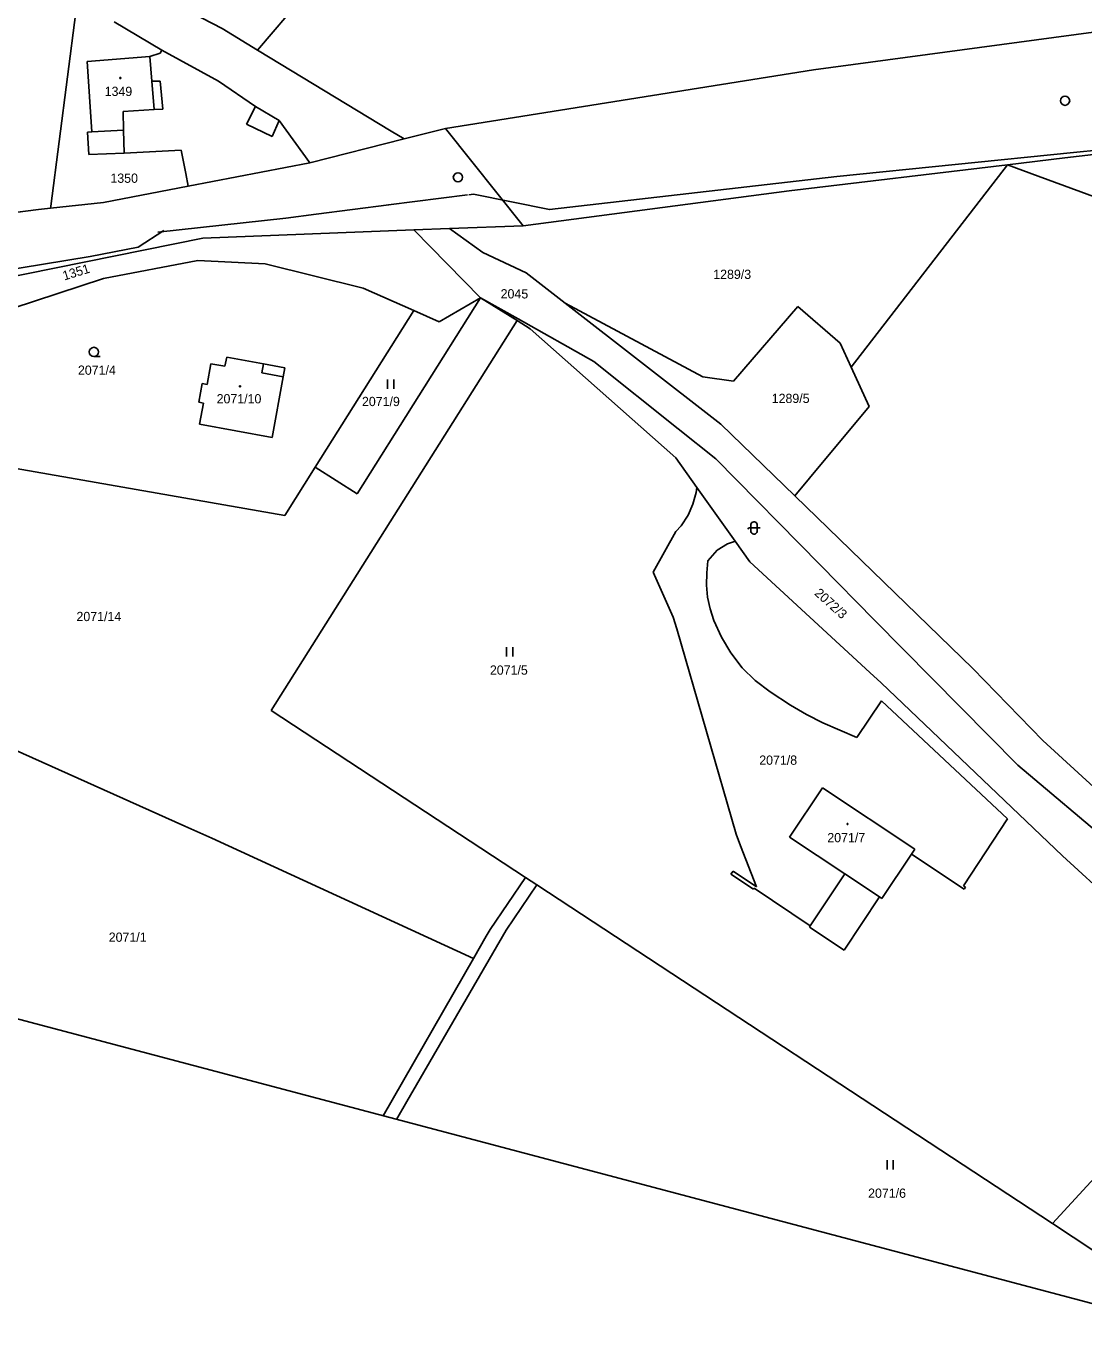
# Model space of a CAD drawing. Extents: x -805011 to -803920, y -1150790 to -1150234.
# Drawn here: x -804600.8 to -804429.5, y -1150682.7 to -1150469 of the extents above; entities that cross this region are included whole.
import ezdxf

# ---------------------------------------------------------------- set-up
doc = ezdxf.new("R2010")
doc.units = 0
for name, color, linetype in [('Default', 7, 'Continuous'), ('formát', 7, 'Continuous'), ('kilometráž - vrstava 7', 7, 'Continuous'), ('kn_celek - Cisla pozemkovych parcel', 7, 'Continuous'), ('kn_celek - Cisla stavebnich parcel', 7, 'Continuous'), ('kn_celek - Hranice parcel', 7, 'Continuous'), ('kn_celek - Vnitrni kresby', 7, 'Continuous'), ('kn_celek - Znacky budov', 7, 'Continuous'), ('kn_celek - Znacky kultur', 7, 'Continuous'), ('plochy - SZDC', 7, 'Continuous'), ('PSR_C2_2_trasa_Vimperk - Kabelová trasa', 7, 'Continuous')]:
    doc.layers.add(name, color=color, linetype=linetype)

# ---------------------------------------------------------------- blocks, each defined once
blk = doc.blocks.new('304')
at = {"layer": 'Default'}
blk.add_line((-0.1, 0), (9.9, 0), dxfattribs=at)
blk.add_circle((-0.1, 7.5), 7.5, dxfattribs=at)
blk = doc.blocks.new('306')
at = {"layer": 'Default'}
for p, q in [((-5.2, 0), (-5.2, 15)), ((4.8, 0), (4.8, 15))]:
    blk.add_line(p, q, dxfattribs=at)
blk = doc.blocks.new('316')
at = {"layer": 'Default'}
for p, q in [((-8.3, 10), (-10, 8.1)), ((-5, 10), (-8.3, 10)), ((-5, 15.5), (-5, 4.5)), ((-5, 10), (5, 10)), ((0.5, 20), (-0.5, 20)), ((-0.5, 0), (0.5, 0)), ((5, 4.5), (5, 15.5)), ((10, 10), (5, 10))]:
    blk.add_line(p, q, dxfattribs=at)
for centre, start, end in [((-0.5, 15.5), 90, 180), ((-0.5, 4.5), 180, 270), ((0.5, 15.5), 0, 90), ((0.5, 4.5), 270, 0)]:
    blk.add_arc(centre, 4.5, start, end, dxfattribs=at)
blk = doc.blocks.new('402')
at = {"layer": 'Default'}
for p, q in [((-0.8, 0.8), (0.7, 0.8)), ((-0.8, 0.8), (-0.8, -0.7)), ((0.7, 0.8), (0.7, -0.7)), ((0.7, -0.7), (-0.8, -0.7))]:
    blk.add_line(p, q, dxfattribs=at)

msp = doc.modelspace()

# ---------------------------------------------------------------- linework, layer by layer
at = {"layer": 'formát'}
msp.add_line((-804402.28, -1150682.7), (-805011.32, -1150521.54), dxfattribs=at)
at = {"layer": 'kilometráž - vrstava 7'}
for centre in [(-804432.47, -1150481.04), (-804530.84, -1150493.45)]:
    msp.add_circle(centre, 0.75, dxfattribs=at)
at = {"layer": 'kn_celek - Hranice parcel'}
for p, q in [((-804584.21, -1150461.47), (-804569.06, -1150469.36)), ((-804556.02, -1150464.26), (-804563.32, -1150472.84)), ((-804592.74, -1150466.72), (-804596.82, -1150498.15)), ((-804578.81, -1150472.86), (-804586.55, -1150468.28)), ((-804563.32, -1150472.84), (-804569.06, -1150469.36)), ((-804427.86, -1150469.92), (-804473.24, -1150476.04)), ((-804590.9, -1150474.67), (-804580.76, -1150473.86)), ((-804590.18, -1150486.09), (-804590.9, -1150474.67)), ((-804579.09, -1150473.33), (-804580.76, -1150473.86)), ((-804578.81, -1150472.86), (-804579.09, -1150473.33)), ((-804569.62, -1150477.9), (-804578.81, -1150472.86)), ((-804563.32, -1150472.84), (-804541.68, -1150485.95)), ((-804473.24, -1150476.04), (-804532.83, -1150485.53)), ((-804563.64, -1150481.97), (-804569.62, -1150477.9)), ((-804559.78, -1150484.23), (-804563.64, -1150481.97)), ((-804559.78, -1150484.23), (-804554.84, -1150491.12)), ((-804590.87, -1150486.13), (-804590.18, -1150486.09)), ((-804590.63, -1150489.77), (-804590.87, -1150486.13)), ((-804554.84, -1150491.12), (-804539.55, -1150487.24)), ((-804541.68, -1150485.95), (-804539.55, -1150487.24)), ((-804539.55, -1150487.24), (-804532.83, -1150485.53)), ((-804520.26, -1150501.29), (-804532.83, -1150485.53)), ((-804584.93, -1150489.54), (-804590.63, -1150489.77)), ((-804584.93, -1150489.54), (-804575.7, -1150489.05)), ((-804575.7, -1150489.05), (-804574.95, -1150492.83)), ((-804413.66, -1150488.07), (-804432.51, -1150490.32)), ((-804574.54, -1150494.89), (-804554.84, -1150491.12)), ((-804441.78, -1150491.42), (-804477.16, -1150495.64)), ((-804467.14, -1150524.2), (-804441.78, -1150491.42)), ((-804432.51, -1150490.32), (-804441.78, -1150491.42)), ((-804436.85, -1150493.24), (-804441.78, -1150491.42)), ((-804574.95, -1150492.83), (-804574.54, -1150494.89)), ((-804436.85, -1150493.24), (-804422.59, -1150498.49)), ((-804574.54, -1150494.89), (-804588.25, -1150497.51)), ((-804520.26, -1150501.29), (-804477.16, -1150495.64)), ((-804596.86, -1150498.46), (-804588.25, -1150497.51)), ((-804596.82, -1150498.15), (-804596.86, -1150498.46)), ((-804621.33, -1150501.45), (-804598.8, -1150498.68)), ((-804596.86, -1150498.46), (-804598.8, -1150498.68)), ((-804537.98, -1150501.97), (-804572.18, -1150503.29)), ((-804532.2, -1150501.75), (-804537.98, -1150501.97)), ((-804537.98, -1150501.97), (-804527.18, -1150512.96)), ((-804532.2, -1150501.75), (-804520.26, -1150501.29)), ((-804532.2, -1150501.75), (-804526.8, -1150505.61)), ((-804621.63, -1150513.27), (-804572.18, -1150503.29)), ((-804526.8, -1150505.61), (-804519.81, -1150508.93)), ((-804588.25, -1150509.82), (-804572.97, -1150506.95)), ((-804572.97, -1150506.95), (-804562.06, -1150507.47)), ((-804562.06, -1150507.47), (-804546.21, -1150511.39)), ((-804603.08, -1150514.69), (-804588.25, -1150509.82)), ((-804519.81, -1150508.93), (-804513.46, -1150513.86)), ((-804547.18, -1150544.7), (-804527.18, -1150512.96)), ((-804546.21, -1150511.39), (-804537.98, -1150515.04)), ((-804527.18, -1150512.96), (-804533.87, -1150516.86)), ((-804521.27, -1150516.66), (-804527.18, -1150512.96)), ((-804521.1, -1150516.38), (-804527.18, -1150512.96)), ((-804537.98, -1150515.04), (-804553.97, -1150540.42)), ((-804533.87, -1150516.86), (-804537.98, -1150515.04)), ((-804513.46, -1150513.86), (-804491.17, -1150525.75)), ((-804513.46, -1150513.86), (-804488.22, -1150533.42)), ((-804486.17, -1150526.47), (-804475.79, -1150514.38)), ((-804475.79, -1150514.38), (-804468.92, -1150520.34)), ((-804521.27, -1150516.66), (-804561.12, -1150579.81)), ((-804519.14, -1150517.99), (-804521.27, -1150516.66)), ((-804508.84, -1150523.27), (-804521.1, -1150516.38)), ((-804495.52, -1150538.89), (-804519.14, -1150517.99)), ((-804468.92, -1150520.34), (-804467.14, -1150524.2)), ((-804571.48, -1150527.02), (-804570.86, -1150523.64)), ((-804570.86, -1150523.64), (-804568.59, -1150524.05)), ((-804568.59, -1150524.05), (-804568.31, -1150522.59)), ((-804568.31, -1150522.59), (-804562.34, -1150523.68)), ((-804562.34, -1150523.68), (-804558.87, -1150524.3)), ((-804495.17, -1150534.18), (-804508.84, -1150523.27)), ((-804559.15, -1150525.77), (-804560.94, -1150535.58)), ((-804558.87, -1150524.3), (-804559.15, -1150525.77)), ((-804491.17, -1150525.75), (-804486.17, -1150526.47)), ((-804467.14, -1150524.2), (-804464.21, -1150530.56)), ((-804572.83, -1150529.87), (-804572.28, -1150526.87)), ((-804572.28, -1150526.87), (-804571.48, -1150527.02)), ((-804572.07, -1150530.01), (-804572.83, -1150529.87)), ((-804572.69, -1150533.42), (-804572.07, -1150530.01)), ((-804464.21, -1150530.56), (-804473.9, -1150542.18)), ((-804560.94, -1150535.58), (-804572.69, -1150533.42)), ((-804489.08, -1150539.04), (-804495.17, -1150534.18)), ((-804476.26, -1150545.02), (-804488.22, -1150533.42)), ((-804558.89, -1150548.22), (-804603.64, -1150540.42)), ((-804553.97, -1150540.42), (-804558.89, -1150548.22)), ((-804553.97, -1150540.42), (-804547.18, -1150544.7)), ((-804492.11, -1150543.68), (-804495.52, -1150538.89)), ((-804472.13, -1150556.23), (-804489.08, -1150539.04)), ((-804473.9, -1150542.18), (-804476.26, -1150545.02)), ((-804492.24, -1150544.49), (-804492.76, -1150546.39)), ((-804492.11, -1150543.68), (-804492.24, -1150544.49)), ((-804485.91, -1150552.4), (-804492.11, -1150543.68)), ((-804447.39, -1150573.04), (-804476.26, -1150545.02)), ((-804492.76, -1150546.39), (-804493.54, -1150548.19)), ((-804493.54, -1150548.19), (-804494.66, -1150549.89)), ((-804495.53, -1150550.85), (-804499.22, -1150557.42)), ((-804494.66, -1150549.89), (-804495.53, -1150550.85)), ((-804488.84, -1150553.87), (-804487.15, -1150552.81)), ((-804487.15, -1150552.81), (-804486.21, -1150552.47)), ((-804486.21, -1150552.47), (-804485.91, -1150552.4)), ((-804483.55, -1150555.72), (-804485.91, -1150552.4)), ((-804490.53, -1150557.54), (-804490.33, -1150555.56)), ((-804490.33, -1150555.56), (-804488.84, -1150553.87)), ((-804483.55, -1150555.72), (-804464.09, -1150573.64)), ((-804499.22, -1150557.42), (-804495.98, -1150564.72)), ((-804490.55, -1150559.51), (-804490.53, -1150557.54)), ((-804472.13, -1150556.23), (-804463.32, -1150565.16)), ((-804490.38, -1150561.47), (-804490.55, -1150559.51)), ((-804489.96, -1150563.35), (-804490.38, -1150561.47)), ((-804489.37, -1150565.26), (-804489.96, -1150563.35)), ((-804495.98, -1150564.72), (-804495.35, -1150566.6)), ((-804488.15, -1150567.96), (-804489.37, -1150565.26)), ((-804440.13, -1150588.68), (-804463.32, -1150565.16)), ((-804495.35, -1150566.6), (-804485.74, -1150599.83)), ((-804486.6, -1150570.5), (-804488.15, -1150567.96)), ((-804484.8, -1150572.89), (-804486.6, -1150570.5)), ((-804482.67, -1150574.98), (-804484.8, -1150572.89)), ((-804480.26, -1150576.8), (-804482.67, -1150574.98)), ((-804464.09, -1150573.64), (-804462.26, -1150575.33)), ((-804436.08, -1150584.68), (-804447.39, -1150573.04)), ((-804476.98, -1150578.97), (-804480.26, -1150576.8)), ((-804462.26, -1150575.33), (-804432.9, -1150603.34)), ((-804474.38, -1150580.45), (-804476.98, -1150578.97)), ((-804462.23, -1150578.26), (-804466.23, -1150584.2)), ((-804441.77, -1150597.39), (-804462.23, -1150578.26)), ((-804561.12, -1150579.81), (-804519.91, -1150606.86)), ((-804471.69, -1150581.79), (-804474.38, -1150580.45)), ((-804575.08, -1150598.55), (-804610.41, -1150582.75)), ((-804468.95, -1150583.03), (-804471.69, -1150581.79)), ((-804466.23, -1150584.2), (-804468.95, -1150583.03)), ((-804415.85, -1150603.25), (-804436.08, -1150584.68)), ((-804440.13, -1150588.68), (-804393.29, -1150628.23)), ((-804477.13, -1150600.34), (-804471.79, -1150592.34)), ((-804471.79, -1150592.34), (-804456.81, -1150602.26)), ((-804570.71, -1150600.51), (-804575.08, -1150598.55)), ((-804448.91, -1150608.23), (-804441.77, -1150597.39)), ((-804570.71, -1150600.51), (-804528.34, -1150620)), ((-804485.74, -1150599.83), (-804485.08, -1150601.74)), ((-804477.13, -1150600.34), (-804468.13, -1150606.27)), ((-804485.08, -1150601.74), (-804482.47, -1150608.37)), ((-804457.37, -1150603.1), (-804456.81, -1150602.26)), ((-804462.13, -1150610.26), (-804457.37, -1150603.1)), ((-804457.37, -1150603.1), (-804448.79, -1150608.78)), ((-804432.9, -1150603.34), (-804404.11, -1150629.75)), ((-804525.63, -1150615.27), (-804519.91, -1150606.86)), ((-804519.91, -1150606.86), (-804518.07, -1150608.06)), ((-804486.25, -1150605.84), (-804486.6, -1150606.33)), ((-804486.6, -1150606.33), (-804482.94, -1150608.77)), ((-804482.47, -1150608.37), (-804486.25, -1150605.84)), ((-804473.53, -1150614.37), (-804468.13, -1150606.27)), ((-804518.07, -1150608.06), (-804523.03, -1150615.38)), ((-804518.07, -1150608.06), (-804434.49, -1150662.92)), ((-804482.94, -1150608.77), (-804482.83, -1150608.6)), ((-804482.83, -1150608.6), (-804473.75, -1150614.7)), ((-804448.58, -1150608.45), (-804448.91, -1150608.23)), ((-804448.79, -1150608.78), (-804448.58, -1150608.45)), ((-804468.27, -1150618.64), (-804462.53, -1150609.99)), ((-804462.53, -1150609.99), (-804462.13, -1150610.26)), ((-804523.03, -1150615.38), (-804539.11, -1150643.15)), ((-804526.25, -1150616.36), (-804525.63, -1150615.27)), ((-804473.75, -1150614.7), (-804473.88, -1150614.9)), ((-804473.88, -1150614.9), (-804468.27, -1150618.64)), ((-804473.75, -1150614.7), (-804473.53, -1150614.37)), ((-804528.34, -1150620), (-804526.25, -1150616.36)), ((-804542.97, -1150645.47), (-804528.34, -1150620)), ((-804434.49, -1150662.92), (-804404.11, -1150629.75)), ((-804539.11, -1150643.15), (-804540.79, -1150646.05)), ((-804407.44, -1150680.8), (-804434.49, -1150662.92))]:
    msp.add_line(p, q, dxfattribs=at)
at = {"layer": 'kn_celek - Vnitrni kresby'}
for p, q in [((-804580.76, -1150473.86), (-804580.44, -1150477.88)), ((-804580.44, -1150477.88), (-804579.07, -1150477.87)), ((-804580.05, -1150482.49), (-804580.44, -1150477.88)), ((-804579.07, -1150477.87), (-804578.68, -1150482.4)), ((-804580.05, -1150482.49), (-804585.1, -1150482.81)), ((-804585.02, -1150485.8), (-804585.1, -1150482.81)), ((-804580.05, -1150482.49), (-804578.68, -1150482.4)), ((-804563.64, -1150481.97), (-804565.11, -1150484.86)), ((-804565.11, -1150484.86), (-804560.95, -1150486.84)), ((-804560.95, -1150486.84), (-804559.78, -1150484.23)), ((-804590.18, -1150486.09), (-804585.02, -1150485.8)), ((-804585.02, -1150485.8), (-804584.93, -1150489.54)), ((-804562.34, -1150523.68), (-804562.63, -1150525.14)), ((-804562.63, -1150525.14), (-804559.15, -1150525.77)), ((-804462.53, -1150609.99), (-804468.13, -1150606.27))]:
    msp.add_line(p, q, dxfattribs=at)
at = {"layer": 'plochy - SZDC'}
for p, q in [((-804427.86, -1150469.92), (-804473.24, -1150476.04)), ((-804473.24, -1150476.04), (-804532.83, -1150485.53)), ((-804539.55, -1150487.24), (-804554.84, -1150491.12)), ((-804532.83, -1150485.53), (-804539.55, -1150487.24)), ((-804532.83, -1150485.53), (-804520.26, -1150501.29)), ((-804520.26, -1150501.29), (-804532.83, -1150485.53)), ((-804432.51, -1150490.32), (-804413.66, -1150488.07)), ((-804554.84, -1150491.12), (-804574.54, -1150494.89)), ((-804477.16, -1150495.64), (-804441.78, -1150491.42)), ((-804441.78, -1150491.42), (-804432.51, -1150490.32)), ((-804574.54, -1150494.89), (-804588.25, -1150497.51)), ((-804520.26, -1150501.29), (-804477.16, -1150495.64)), ((-804588.25, -1150497.51), (-804596.86, -1150498.46)), ((-804598.8, -1150498.68), (-804621.33, -1150501.45)), ((-804596.86, -1150498.46), (-804598.8, -1150498.68)), ((-804572.18, -1150503.29), (-804537.98, -1150501.97)), ((-804537.98, -1150501.97), (-804532.2, -1150501.75)), ((-804532.2, -1150501.75), (-804520.26, -1150501.29)), ((-804621.63, -1150513.27), (-804572.18, -1150503.29))]:
    msp.add_line(p, q, dxfattribs=at)
at = {"layer": 'PSR_C2_2_trasa_Vimperk - Kabelová trasa'}
for p, q in [((-804542.06, -1150497.91), (-804553.82, -1150499.4)), ((-804529.29, -1150496.27), (-804542.1, -1150497.89)), ((-804558.71, -1150500.08), (-804579.48, -1150502.32)), ((-804558.71, -1150500.08), (-804553.82, -1150499.4)), ((-804582.65, -1150504.79), (-804578.5, -1150502.04)), ((-804617.64, -1150510.74), (-804590.41, -1150506.27)), ((-804582.65, -1150504.79), (-804590.41, -1150506.27))]:
    msp.add_line(p, q, dxfattribs=at)
msp.add_lwpolyline([(-804529.08, -1150496.27), (-804528.3, -1150496.2), (-804516.01, -1150498.69), (-804469.46, -1150493.33), (-804431.1, -1150489.42), (-804404.84, -1150486.85), (-804374.84, -1150483.32), (-804363.68, -1150482.47), (-804347.01, -1150481.54), (-804340.82, -1150481.2), (-804326.33, -1150481.6), (-804317.79, -1150482), (-804308.33, -1150484.14), (-804289, -1150488.51)], dxfattribs=at)

# ---------------------------------------------------------------- block references
at = {"layer": 'kn_celek - Znacky budov', "xscale": 0.1, "yscale": 0.10000000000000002}
for p in [(-804585.55, -1150477.36), (-804566.14, -1150527.32), (-804467.72, -1150598.21)]:
    msp.add_blockref('402', p, dxfattribs=at)
at = {"layer": 'kn_celek - Znacky kultur', "xscale": 0.1, "yscale": 0.10000000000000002}
for name, p in [('304', (-804589.82, -1150522.49)), ('306', (-804541.72, -1150527.71)), ('316', (-804482.86, -1150551.25)), ('306', (-804522.44, -1150571.08)), ('306', (-804460.79, -1150654.16))]:
    msp.add_blockref(name, p, dxfattribs=at)

# ---------------------------------------------------------------- texts
at = {"layer": 'kn_celek - Cisla pozemkovych parcel'}
for s, p in [('1350', (-804587.15, -1150494.34)), ('1289/3', (-804489.47, -1150509.91)), ('2045', (-804523.92, -1150513.07)), ('2071/4', (-804592.41, -1150525.44)), ('2071/9', (-804546.39, -1150530.51)), ('1289/5', (-804480, -1150530.01)), ('2071/14', (-804592.65, -1150565.34)), ('2071/5', (-804525.66, -1150574.02)), ('2071/8', (-804482.02, -1150588.61)), ('2071/1', (-804587.42, -1150617.29)), ('2071/6', (-804464.38, -1150658.76))]:
    msp.add_text(s, height=1.5, dxfattribs=at).set_placement(p)
for s, rotation, p in [('1351', 17.1, (-804594.63, -1150510.17)), ('2072/3', 317.9525, (-804473.18, -1150560.98))]:
    msp.add_text(s, height=1.5, rotation=rotation, dxfattribs=at).set_placement(p)
at = {"layer": 'kn_celek - Cisla stavebnich parcel'}
for s, p in [('1349', (-804588.08, -1150480.28)), ('2071/10', (-804569.94, -1150530.07)), ('2071/7', (-804470.99, -1150601.16))]:
    msp.add_text(s, height=1.5, dxfattribs=at).set_placement(p)

doc.saveas('drawing.dxf')
